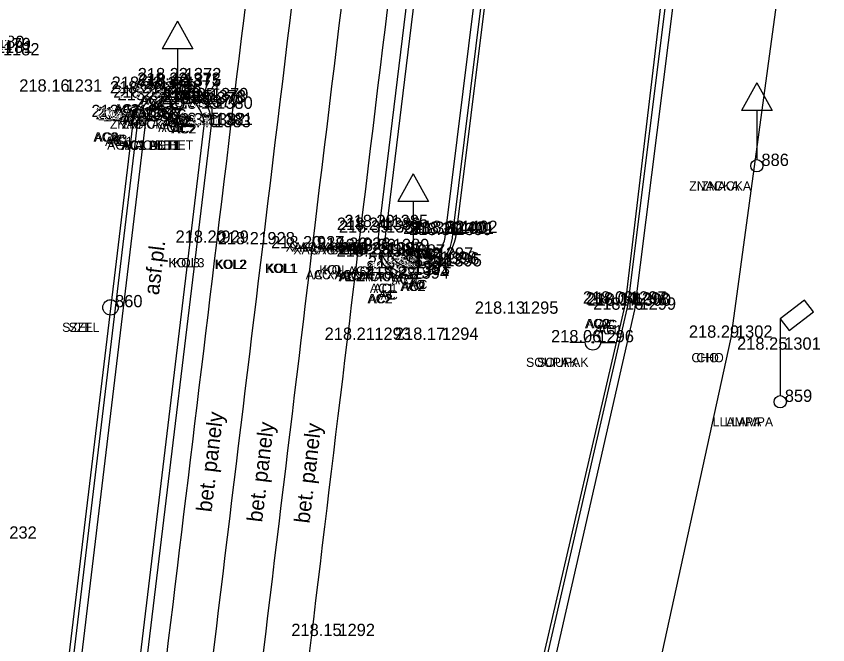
# Model space of a CAD drawing. Extents: x -471047 to -470889, y -1102859 to -1102000.
# Drawn here: x -470973.87 to -470947.45, y -1102478.75 to -1102458.3 of the extents above; entities that cross this region are included whole.
import ezdxf

# ---------------------------------------------------------------- set-up
doc = ezdxf.new("R2010")
doc.units = 0
for name, color, linetype in [('Vrstva 1', 7, 'Continuous'), ('Vrstva 11', 7, 'Continuous'), ('Vrstva 19', 7, 'Continuous'), ('Vrstva 22', 7, 'Continuous'), ('Vrstva 23', 7, 'Continuous'), ('Vrstva 34', 7, 'Continuous'), ('Vrstva 35', 7, 'Continuous'), ('Vrstva 36', 7, 'Continuous'), ('Vrstva 38', 7, 'Continuous'), ('Vrstva 5', 7, 'Continuous'), ('Vrstva 7', 7, 'Continuous'), ('Vrstva 8', 7, 'Continuous')]:
    doc.layers.add(name, color=color, linetype=linetype)

msp = doc.modelspace()

# ---------------------------------------------------------------- linework, layer by layer
at = {"layer": 'Vrstva 1'}
for points in [[(-471040.344, -1102858.385), (-471031.676, -1102846.187), (-471026.357, -1102838.629), (-471023.212, -1102833.975), (-471019.21, -1102827.465), (-471016.861, -1102823.272), (-471013.099, -1102815.912), (-471010.824, -1102810.955), (-471007.329, -1102802.292), (-471005.34, -1102796.515), (-471002.842, -1102787.838), (-471001.3, -1102780.997), (-471000.19, -1102774.713), (-470999.247, -1102768.204), (-470998.794, -1102764.784), (-470997.199, -1102751.812), (-470994.899, -1102732.807), (-470992.551, -1102713.262), (-470990.326, -1102694.887), (-470988.122, -1102676.57), (-470985.812, -1102657.305), (-470983.537, -1102638.407), (-470981.386, -1102620.622), (-470979.843, -1102608.014), (-470976.377, -1102579.253), (-470972.945, -1102550.69), (-470970.475, -1102530.206), (-470967.905, -1102508.801), (-470965.053, -1102485.131), (-470962.734, -1102465.9), (-470960.173, -1102444.812), (-470957.795, -1102425.103), (-470954.965, -1102401.839), (-470953.834, -1102392.574), (-470952.33, -1102379.985), (-470950.744, -1102366.853), (-470948.978, -1102352.106), (-470947.037, -1102335.844), (-470944.949, -1102318.462), (-470944.013, -1102310.745), (-470942.39, -1102297.267), (-470939.519, -1102273.45), (-470937.593, -1102257.43), (-470936.064, -1102244.81), (-470934.114, -1102228.634), (-470931.621, -1102207.856), (-470929.536, -1102190.857), (-470926.572, -1102166.31), (-470924.91, -1102152.663), (-470923.413, -1102140.333), (-470921.923, -1102127.669), (-470921.155, -1102120.084), (-470920.446, -1102109.574), (-470919.912, -1102099.137), (-470919.63, -1102088.981), (-470919.523, -1102081.193), (-470919.563, -1102070.395), (-470919.714, -1102064.236), (-470920.134, -1102054.704), (-470920.462, -1102047.615), (-470920.599, -1102044.52), (-470920.743, -1102041.873), (-470921.125, -1102034.455), (-470921.774, -1102030.337), (-470922.418, -1102027.787), (-470923.734, -1102023.93), (-470924.872, -1102021.434), (-470926.752, -1102018.182), (-470927.953, -1102016.45), (-470929.616, -1102014.424), (-470932.252, -1102011.756), (-470935.111, -1102009.425), (-470938.391, -1102007.371), (-470942.651, -1102005.401)], [(-471041.328, -1102857.18), (-471032.144, -1102844.242), (-471027.583, -1102837.763), (-471024.388, -1102833.028), (-471020.451, -1102826.6), (-471018.089, -1102822.378), (-471014.542, -1102815.445), (-471012.233, -1102810.418), (-471009.247, -1102803.108), (-471006.795, -1102796.098), (-471004.315, -1102787.532), (-471002.782, -1102780.723), (-471001.674, -1102774.458), (-471000.75, -1102768.095), (-471000.28, -1102764.601), (-470998.692, -1102751.741), (-470996.378, -1102732.635), (-470994.028, -1102713.058), (-470991.808, -1102694.749), (-470989.616, -1102676.447), (-470987.284, -1102657.013), (-470985.031, -1102638.272), (-470982.87, -1102620.431), (-470981.334, -1102607.933), (-470977.881, -1102579.263), (-470974.429, -1102550.492), (-470971.964, -1102530.054), (-470969.391, -1102508.607), (-470966.54, -1102484.984), (-470964.231, -1102465.853), (-470961.679, -1102444.752), (-470959.304, -1102425.078), (-470956.455, -1102401.634), (-470955.339, -1102392.489), (-470953.812, -1102379.71), (-470952.249, -1102366.808), (-470950.479, -1102352.023), (-470948.536, -1102335.868), (-470946.426, -1102318.233), (-470945.493, -1102310.531), (-470943.864, -1102297.013), (-470940.984, -1102273.071), (-470939.078, -1102257.195), (-470937.559, -1102244.684), (-470935.592, -1102228.353), (-470933.101, -1102207.653), (-470931.011, -1102190.57), (-470928.046, -1102166.021), (-470926.409, -1102152.578), (-470924.898, -1102140.121), (-470923.427, -1102127.544), (-470922.647, -1102119.826), (-470921.919, -1102109.229), (-470921.42, -1102099.134), (-470921.127, -1102089.016), (-470921.023, -1102081.453), (-470921.061, -1102070.468), (-470921.209, -1102064.314), (-470921.666, -1102053.966), (-470922.156, -1102043.345), (-470922.299, -1102039.934), (-470922.637, -1102034.36), (-470923.091, -1102031.241), (-470923.847, -1102028.247), (-470925.083, -1102024.594), (-470926.222, -1102022.086), (-470928.04, -1102018.943), (-470929.138, -1102017.357), (-470930.929, -1102015.175), (-470933.062, -1102013.049), (-470936.379, -1102010.368), (-470939.169, -1102008.662), (-470942.899, -1102006.906), (-470945.661, -1102005.908)], [(-471043.557, -1102855.955), (-471035.129, -1102844.026), (-471029.872, -1102836.499), (-471026.577, -1102831.578), (-471022.675, -1102825.415), (-471020.123, -1102821.053), (-471016.667, -1102814.59), (-471014.208, -1102809.45), (-471011.177, -1102802.451), (-471008.55, -1102795.333), (-471006.082, -1102787.209), (-471004.464, -1102780.376), (-471003.265, -1102774.167), (-471002.327, -1102767.948), (-471001.636, -1102762.527), (-471000.297, -1102751.605), (-470997.959, -1102732.524), (-470995.602, -1102712.802), (-470993.412, -1102694.623), (-470991.21, -1102676.17), (-470988.891, -1102656.857), (-470986.625, -1102638.083), (-470984.455, -1102620.195), (-470982.936, -1102607.733), (-470979.497, -1102579.223), (-470976.023, -1102550.279), (-470973.554, -1102529.822), (-470970.991, -1102508.497), (-470968.146, -1102484.787), (-470965.835, -1102465.72), (-470963.284, -1102444.529), (-470960.91, -1102424.942), (-470958.043, -1102401.343), (-470956.946, -1102392.356), (-470955.396, -1102379.408), (-470953.851, -1102366.636), (-470952.049, -1102351.733), (-470950.124, -1102335.611), (-470948.034, -1102318.083), (-470947.094, -1102310.328), (-470945.421, -1102296.51), (-470942.58, -1102272.848), (-470940.675, -1102256.948), (-470939.176, -1102244.526), (-470937.187, -1102228.174), (-470934.708, -1102207.467), (-470932.621, -1102190.433), (-470929.634, -1102165.778), (-470928.004, -1102152.415), (-470926.45, -1102139.595), (-470925.003, -1102127.418), (-470924.249, -1102119.695), (-470923.515, -1102109.093), (-470923.018, -1102099.069), (-470922.711, -1102088.911), (-470922.643, -1102081.356), (-470922.797, -1102070.414), (-470923.018, -1102064.454), (-470923.52, -1102053.203), (-470923.823, -1102047.529), (-470924.123, -1102041.506), (-470924.462, -1102037.486), (-470924.934, -1102031.904), (-470925.664, -1102028.672), (-470926.771, -1102025.506), (-470927.959, -1102022.914), (-470929.674, -1102020.028), (-470930.76, -1102018.498), (-470932.447, -1102016.478), (-470935.215, -1102013.816), (-470937.644, -1102011.98), (-470940.381, -1102010.371), (-470943.968, -1102008.669), (-470947.145, -1102007.524), (-470950.874, -1102006.74)], [(-471044.756, -1102855.056), (-471036.376, -1102843.177), (-471031.167, -1102835.741), (-471027.859, -1102830.8), (-471023.934, -1102824.593), (-471021.43, -1102820.312), (-471018.011, -1102813.91), (-471015.536, -1102808.75), (-471012.578, -1102801.897), (-471009.95, -1102794.77), (-471007.561, -1102786.914), (-471005.936, -1102780.074), (-471004.727, -1102773.818), (-471003.828, -1102767.827), (-471003.121, -1102762.345), (-471001.787, -1102751.467), (-470999.446, -1102732.348), (-470997.073, -1102712.539), (-470994.902, -1102694.521), (-470992.696, -1102676.023), (-470990.376, -1102656.68), (-470988.131, -1102638.071), (-470985.947, -1102620.018), (-470984.417, -1102607.512), (-470980.993, -1102579.08), (-470977.514, -1102550.137), (-470975.048, -1102529.649), (-470972.488, -1102508.37), (-470969.618, -1102484.508), (-470967.34, -1102465.669), (-470964.767, -1102444.39), (-470962.402, -1102424.781), (-470959.534, -1102401.193), (-470958.432, -1102392.151), (-470956.883, -1102379.208), (-470955.335, -1102366.424), (-470953.535, -1102351.506), (-470951.606, -1102335.399), (-470949.519, -1102317.94), (-470948.575, -1102310.159), (-470946.889, -1102296.144), (-470944.056, -1102272.618), (-470942.139, -1102256.659), (-470940.657, -1102244.341), (-470938.638, -1102227.749), (-470936.19, -1102207.298), (-470934.102, -1102190.255), (-470931.124, -1102165.639), (-470929.492, -1102152.254), (-470927.915, -1102139.252), (-470926.46, -1102127.103), (-470925.74, -1102119.604), (-470925.012, -1102108.913), (-470924.523, -1102099.054), (-470924.217, -1102088.866), (-470924.148, -1102081.334), (-470924.301, -1102070.391), (-470924.518, -1102064.43), (-470924.97, -1102054.435), (-470925.588, -1102041.569), (-470925.963, -1102035.313), (-470926.405, -1102032.225), (-470927.078, -1102029.198), (-470928.123, -1102026.148), (-470929.318, -1102023.558), (-470930.84, -1102020.97), (-470931.868, -1102019.515), (-470933.443, -1102017.605), (-470936.26, -1102014.885), (-470938.429, -1102013.255), (-470941.213, -1102011.639), (-470944.847, -1102009.927), (-470947.723, -1102008.912), (-470951.444, -1102008.161), (-470954.511, -1102007.931), (-470957.895, -1102008.041)]]:
    msp.add_spline(points, degree=3, dxfattribs=at)
at = {"layer": 'Vrstva 11'}
for p, q in [((-470955.349, -1102468.912), (-470955.849, -1102468.912)), ((-470954.849, -1102468.912), (-470954.349, -1102468.912))]:
    msp.add_line(p, q, dxfattribs=at)
for radius in [0.25, 0.025]:
    msp.add_circle((-470955.099, -1102468.912), radius, dxfattribs=at)
at = {"layer": 'Vrstva 19'}
for p, q in [((-470968.617, -1102458.459), (-470969.117, -1102459.359)), ((-470968.617, -1102458.459), (-470968.117, -1102459.359)), ((-470968.117, -1102459.359), (-470969.117, -1102459.359)), ((-470968.617, -1102459.359), (-470968.617, -1102460.959)), ((-470949.762, -1102460.465), (-470950.262, -1102461.365)), ((-470949.762, -1102460.465), (-470949.262, -1102461.365)), ((-470949.262, -1102461.365), (-470950.262, -1102461.365)), ((-470949.762, -1102461.365), (-470949.762, -1102462.965)), ((-470960.945, -1102463.422), (-470961.445, -1102464.322)), ((-470960.945, -1102463.422), (-470960.445, -1102464.322)), ((-470960.445, -1102464.322), (-470961.445, -1102464.322)), ((-470960.945, -1102464.322), (-470960.945, -1102465.922))]:
    msp.add_line(p, q, dxfattribs=at)
for centre in [(-470968.617, -1102461.159), (-470949.762, -1102463.165), (-470960.945, -1102466.122)]:
    msp.add_circle(centre, 0.2, dxfattribs=at)
at = {"layer": 'Vrstva 23'}
for p, q in [((-470948.206, -1102467.541), (-470949.001, -1102468.146)), ((-470947.916, -1102467.918), (-470948.206, -1102467.541)), ((-470948.714, -1102468.524), (-470947.916, -1102467.918)), ((-470949.001, -1102468.146), (-470949.001, -1102470.646)), ((-470949.001, -1102468.146), (-470948.714, -1102468.524))]:
    msp.add_line(p, q, dxfattribs=at)
for centre, radius in [((-470970.801, -1102467.773), 0.25), ((-470949.001, -1102470.846), 0.2)]:
    msp.add_circle(centre, radius, dxfattribs=at)
at = {"layer": 'Vrstva 34'}
for p, q in [((-470968.53, -1102460.38), (-470968.53, -1102460.38)), ((-470969.38, -1102460.66), (-470969.38, -1102460.66)), ((-470968.55, -1102460.53), (-470968.55, -1102460.53)), ((-470968.54, -1102460.58), (-470968.54, -1102460.58)), ((-470972.41, -1102460.75), (-470972.41, -1102460.75)), ((-470969.35, -1102460.81), (-470969.35, -1102460.81)), ((-470969.35, -1102460.95), (-470969.35, -1102460.95)), ((-470968.58, -1102460.78), (-470968.58, -1102460.78)), ((-470969.21, -1102461.03), (-470969.21, -1102461.03)), ((-470968.62, -1102461.16), (-470968.62, -1102461.16)), ((-470967.93, -1102461.26), (-470967.93, -1102461.26)), ((-470967.8, -1102461.16), (-470967.8, -1102461.16)), ((-470967.73, -1102461.1), (-470967.73, -1102461.1)), ((-470967.65, -1102461.03), (-470967.65, -1102461.03)), ((-470967.51, -1102461.31), (-470967.51, -1102461.31)), ((-470970.04, -1102461.58), (-470970.04, -1102461.58)), ((-470969.9, -1102461.65), (-470969.9, -1102461.65)), ((-470969.83, -1102461.68), (-470969.83, -1102461.68)), ((-470969.66, -1102461.72), (-470969.66, -1102461.72)), ((-470967.75, -1102461.85), (-470967.75, -1102461.85)), ((-470967.57, -1102461.91), (-470967.57, -1102461.91)), ((-470967.51, -1102461.84), (-470967.51, -1102461.84)), ((-470949.76, -1102463.17), (-470949.76, -1102463.17)), ((-470961.8, -1102465.16), (-470961.8, -1102465.16)), ((-470962.05, -1102465.25), (-470962.05, -1102465.25)), ((-470961.98, -1102465.34), (-470961.98, -1102465.34)), ((-470959.89, -1102465.38), (-470959.89, -1102465.38)), ((-470959.72, -1102465.42), (-470959.72, -1102465.42)), ((-470959.66, -1102465.38), (-470959.66, -1102465.38)), ((-470959.54, -1102465.35), (-470959.54, -1102465.35)), ((-470967.34, -1102465.67), (-470967.34, -1102465.67)), ((-470965.84, -1102465.72), (-470965.84, -1102465.72)), ((-470964.23, -1102465.85), (-470964.23, -1102465.85)), ((-470962.73, -1102465.9), (-470962.73, -1102465.9)), ((-470961.76, -1102465.94), (-470961.76, -1102465.94)), ((-470962.06, -1102466.12), (-470962.06, -1102466.12)), ((-470961.97, -1102466.06), (-470961.97, -1102466.06)), ((-470961.92, -1102466.05), (-470961.92, -1102466.05)), ((-470960.95, -1102466.12), (-470960.95, -1102466.12)), ((-470960.33, -1102466.22), (-470960.33, -1102466.22)), ((-470961.04, -1102466.5), (-470961.04, -1102466.5)), ((-470960.22, -1102466.35), (-470960.22, -1102466.35)), ((-470960.13, -1102466.38), (-470960.13, -1102466.38)), ((-470960.05, -1102466.44), (-470960.05, -1102466.44)), ((-470961.09, -1102466.66), (-470961.09, -1102466.66)), ((-470961.09, -1102466.72), (-470961.09, -1102466.72)), ((-470961.12, -1102466.84), (-470961.12, -1102466.84)), ((-470970.8, -1102467.77), (-470970.8, -1102467.77)), ((-470954.04, -1102467.65), (-470954.04, -1102467.65)), ((-470953.95, -1102467.68), (-470953.95, -1102467.68)), ((-470953.89, -1102467.72), (-470953.89, -1102467.72)), ((-470953.73, -1102467.85), (-470953.73, -1102467.85)), ((-470957.56, -1102467.98), (-470957.56, -1102467.98)), ((-470962.36, -1102468.83), (-470962.36, -1102468.83)), ((-470960.16, -1102468.83), (-470960.16, -1102468.83)), ((-470955.1, -1102468.91), (-470955.1, -1102468.91)), ((-470950.59, -1102468.76), (-470950.59, -1102468.76)), ((-470949.02, -1102469.15), (-470949.02, -1102469.15)), ((-470949, -1102470.85), (-470949, -1102470.85)), ((-470963.53, -1102478.47), (-470963.53, -1102478.47))]:
    msp.add_line(p, q, dxfattribs=at)
at = {"layer": 'Vrstva 5'}
for p, q in [((-470959.536, -1102465.35), (-470957.491, -1102448.938)), ((-470954.037, -1102467.653), (-470951.83, -1102449.069)), ((-470967.507, -1102461.31), (-470967.509, -1102461.842)), ((-470972.503, -1102482.091), (-470970.044, -1102461.58)), ((-470961.965, -1102466.061), (-470962.062, -1102466.116)), ((-470956.777, -1102479.435), (-470954.037, -1102467.653))]:
    msp.add_line(p, q, dxfattribs=at)
for centre, radius, start, end in [((-470968.456, -1102462.026), 1.649, 92.6792, 164.3252), ((-470968.922, -1102461.837), 1.509, 20.4159, 75.0812)]:
    msp.add_arc(centre, radius, start, end, dxfattribs=at)
at = {"layer": 'Vrstva 7'}
for p, q in [((-470961.805, -1102465.162), (-470959.783, -1102448.626)), ((-470959.894, -1102465.384), (-470957.865, -1102448.933)), ((-470953.729, -1102467.848), (-470951.395, -1102449.228)), ((-470972.098, -1102482.131), (-470969.655, -1102461.72)), ((-470970.234, -1102482.541), (-470967.747, -1102461.853)), ((-470956.386, -1102479.473), (-470953.729, -1102467.848))]:
    msp.add_line(p, q, dxfattribs=at)
for centre, radius, start, end in [((-470968.456, -1102462.006), 1.232, 95.668, 166.5606), ((-470968.897, -1102461.885), 1.15, 1.5947, 73.9183), ((-470960.828, -1102465.491), 1.031, 161.3791, 257.9166), ((-470961.109, -1102465.282), 1.219, 273.0505, 355.179)]:
    msp.add_arc(centre, radius, start, end, dxfattribs=at)
at = {"layer": 'Vrstva 8'}
for p, q in [((-470962.05, -1102465.251), (-470960.033, -1102448.587)), ((-470959.656, -1102465.384), (-470957.621, -1102448.918)), ((-470953.953, -1102467.677), (-470951.633, -1102449.156)), ((-470950.592, -1102468.764), (-470948.019, -1102449.764)), ((-470972.348, -1102482.071), (-470969.899, -1102461.647)), ((-470970.009, -1102482.55), (-470967.509, -1102461.842)), ((-470956.653, -1102479.445), (-470953.953, -1102467.677)), ((-470953.088, -1102480.135), (-470950.592, -1102468.764))]:
    msp.add_line(p, q, dxfattribs=at)
for centre, radius, start, end in [((-470968.507, -1102461.955), 1.425, 91.9216, 167.5384), ((-470968.831, -1102461.823), 1.322, 359.1738, 77.9539), ((-470960.884, -1102465.538), 1.201, 166.1717, 260.3049), ((-470961.05, -1102465.328), 1.395, 268.5039, 357.6888), ((-470961.545, -1102465.061), 2.029, 317.2268, 351.8097), ((-470960.958, -1102465.652), 1.197, 202.7767, 318.9381)]:
    msp.add_arc(centre, radius, start, end, dxfattribs=at)

# ---------------------------------------------------------------- texts
at = {"layer": 'Vrstva 22'}
for s, rotation, p in [('asf.pl.', 83.0293, (-470969.229, -1102467.39)), ('bet. panely', 83.1381, (-470967.513, -1102474.453)), ('bet. panely', 83.1381, (-470965.864, -1102474.782)), ('bet. panely', 83.1381, (-470964.325, -1102474.819))]:
    msp.add_text(s, height=0.5, rotation=rotation, dxfattribs=at).set_placement(p)
at = {"layer": 'Vrstva 35'}
for s, p in [('AC2', (-470969.846, -1102461.18)), ('AC2', (-470969.805, -1102461.18)), ('AC2', (-470970.696, -1102461.46)), ('AC2', (-470970.655, -1102461.46)), ('AC1', (-470969.897, -1102461.58)), ('AC1', (-470969.78, -1102461.58)), ('AC', (-470969.539, -1102461.33)), ('AC', (-470969.464, -1102461.33)), ('AC1', (-470970.527, -1102461.83)), ('AC1', (-470970.41, -1102461.83)), ('AC', (-470970.339, -1102461.61)), ('AC', (-470970.264, -1102461.61)), ('AC2', (-470968.966, -1102461.83)), ('AC2', (-470968.925, -1102461.83)), ('ZNACKA', (-470970.82, -1102461.96)), ('ZNACKA', (-470970.434, -1102461.96)), ('AC1', (-470969.247, -1102462.06)), ('AC1', (-470969.13, -1102462.06)), ('AC2', (-470968.826, -1102462.11)), ('AC2', (-470968.785, -1102462.11)), ('AC', (-470968.719, -1102461.9)), ('AC', (-470968.644, -1102461.9)), ('AC2', (-470971.356, -1102462.38)), ('AC2', (-470971.315, -1102462.38)), ('AC1', (-470970.977, -1102462.52)), ('AC', (-470970.889, -1102462.45)), ('AC1', (-470970.86, -1102462.52)), ('AC', (-470970.814, -1102462.45)), ('AC2 AC BET', (-470970.91, -1102462.64)), ('AC2 AC BET', (-470970.45, -1102462.64)), ('AC1 BET1', (-470970.45, -1102462.65)), ('AC1 BET1', (-470970.417, -1102462.65)), ('ZNACKA', (-470951.96, -1102463.97)), ('ZNACKA', (-470951.574, -1102463.97)), ('XAC1 XBET1', (-470965.1, -1102465.96)), ('XAC1 XBET1', (-470964.917, -1102465.96)), ('XAC XBET', (-470964.85, -1102466.05)), ('XAC XBET', (-470964.314, -1102466.05)), ('AC1', (-470961.207, -1102466.18)), ('AC1', (-470961.09, -1102466.18)), ('AC2', (-470960.856, -1102466.15)), ('AC2', (-470960.815, -1102466.15)), ('AC', (-470960.649, -1102466.18)), ('AC', (-470960.574, -1102466.18)), ('KOL3', (-470968.915, -1102466.47)), ('KOL3', (-470968.768, -1102466.47)), ('KOL2', (-470967.415, -1102466.52)), ('KOL2', (-470967.381, -1102466.52)), ('KOL1', (-470965.772, -1102466.65)), ('KOL1', (-470965.73, -1102466.65)), ('AC XAC2', (-470964.445, -1102466.86)), ('AC XAC2', (-470964.186, -1102466.86)), ('KOL', (-470964.005, -1102466.7)), ('KOL', (-470963.869, -1102466.7)), ('AC1', (-470963.077, -1102466.74)), ('AC1', (-470962.96, -1102466.74)), ('AC2', (-470963.376, -1102466.92)), ('AC2', (-470963.335, -1102466.92)), ('ZNACKA', (-470963.15, -1102466.92)), ('ZNACKA', (-470962.764, -1102466.92)), ('AC1', (-470961.647, -1102467.02)), ('AC1', (-470961.53, -1102467.02)), ('AC1', (-470962.357, -1102467.3)), ('AC1', (-470962.24, -1102467.3)), ('AC2', (-470961.366, -1102467.24)), ('AC2', (-470961.325, -1102467.24)), ('AC', (-470961.119, -1102467.18)), ('AC', (-470961.044, -1102467.18)), ('AC2', (-470962.436, -1102467.64)), ('AC2', (-470962.395, -1102467.64)), ('AC', (-470962.079, -1102467.52)), ('AC', (-470962.004, -1102467.52)), ('AC2', (-470955.356, -1102468.45)), ('AC2', (-470955.315, -1102468.45)), ('SZEL', (-470972.375, -1102468.57)), ('SZEL', (-470972.164, -1102468.57)), ('AC1', (-470955.047, -1102468.65)), ('AC', (-470954.939, -1102468.48)), ('AC1', (-470954.93, -1102468.65)), ('AC', (-470954.864, -1102468.48)), ('SOUPAK', (-470957.275, -1102469.71)), ('SOUPAK', (-470956.914, -1102469.71)), ('CHO', (-470951.891, -1102469.56)), ('CHO', (-470951.729, -1102469.56)), ('LLAMPA', (-470951.2, -1102471.65)), ('LLAMPA', (-470950.814, -1102471.65))]:
    msp.add_text(s, height=0.3, dxfattribs=at).set_placement(p)
at = {"layer": 'Vrstva 36'}
for s, p in [(' 1180', (-470974.94, -1102459.33)), (' 1179', (-470974.73, -1102459.4)), (' 1181', (-470974.68, -1102459.49)), (' 1182', (-470974.45, -1102459.57)), (' 1373', (-470968.55, -1102460.53)), (' 1375', (-470968.54, -1102460.58)), (' 1372', (-470968.53, -1102460.38)), (' 1231', (-470972.41, -1102460.75)), (' 1371', (-470969.38, -1102460.66)), (' 1370', (-470969.35, -1102460.81)), (' 1374', (-470968.58, -1102460.78)), (' 1368', (-470969.35, -1102460.95)), (' 1369', (-470969.21, -1102461.03)), (' 1378', (-470967.73, -1102461.1)), (' 1379', (-470967.65, -1102461.03)), (' 888', (-470968.62, -1102461.16)), (' 1377', (-470967.93, -1102461.26)), (' 1376', (-470967.8, -1102461.16)), (' 1380', (-470967.51, -1102461.31)), (' 1364', (-470970.04, -1102461.58)), (' 1365', (-470969.9, -1102461.65)), (' 1367', (-470969.83, -1102461.68)), (' 1366', (-470969.66, -1102461.72)), (' 1382', (-470967.75, -1102461.85)), (' 1383', (-470967.57, -1102461.91)), (' 1381', (-470967.51, -1102461.84)), (' 886', (-470949.76, -1102463.17)), (' 1386', (-470962.05, -1102465.25)), (' 1384', (-470961.98, -1102465.34)), (' 1385', (-470961.8, -1102465.16)), (' 1400', (-470959.89, -1102465.38)), (' 1401', (-470959.66, -1102465.38)), (' 1402', (-470959.54, -1102465.35)), (' 1399', (-470959.72, -1102465.42)), (' 929', (-470967.34, -1102465.67)), (' 928', (-470965.84, -1102465.72)), (' 927', (-470964.23, -1102465.85)), (' 926', (-470962.73, -1102465.9)), (' 1388', (-470962.06, -1102466.12)), (' 1387', (-470961.97, -1102466.06)), (' 1390', (-470961.92, -1102466.05)), (' 1389', (-470961.76, -1102465.94)), (' 887', (-470960.95, -1102466.12)), (' 1397', (-470960.33, -1102466.22)), (' 1398', (-470960.22, -1102466.35)), (' 1396', (-470960.13, -1102466.38)), (' 1391', (-470961.09, -1102466.66)), (' 1392', (-470961.04, -1102466.5)), (' 1395', (-470960.05, -1102466.44)), (' 1394', (-470961.12, -1102466.84)), (' 1393', (-470961.09, -1102466.72)), (' 1297', (-470954.04, -1102467.65)), (' 1298', (-470953.95, -1102467.68)), (' 1300', (-470953.89, -1102467.72)), (' 860', (-470970.8, -1102467.77)), (' 1295', (-470957.56, -1102467.98)), (' 1299', (-470953.73, -1102467.85)), (' 1302', (-470950.59, -1102468.76)), (' 1293', (-470962.36, -1102468.83)), (' 1294', (-470960.16, -1102468.83)), (' 1296', (-470955.1, -1102468.91)), (' 1301', (-470949.02, -1102469.15)), (' 859', (-470949, -1102470.85)), (' 1232', (-470974.54, -1102475.3)), (' 1292', (-470963.53, -1102478.47))]:
    msp.add_text(s, height=0.4, dxfattribs=at).set_placement(p)
at = {"layer": 'Vrstva 38'}
for s, p in [('218.22 ', (-470969.931, -1102460.53)), ('218.23 ', (-470969.913, -1102460.38)), ('218.40 ', (-470969.883, -1102460.58)), ('218.16 ', (-470973.77, -1102460.75)), ('218.21 ', (-470970.82, -1102460.81)), ('218.23 ', (-470970.763, -1102460.66)), ('218.38 ', (-470969.964, -1102460.78)), ('218.36 ', (-470970.71, -1102460.95)), ('218.36 ', (-470970.57, -1102461.03)), ('218.25 ', (-470969.114, -1102461.1)), ('218.25 ', (-470969.034, -1102461.03)), ('218.39 ', (-470969.314, -1102461.26)), ('218.40 ', (-470969.143, -1102461.16)), ('218.25 ', (-470968.894, -1102461.31)), ('218.19 ', (-470971.424, -1102461.58)), ('218.18 ', (-470971.284, -1102461.65)), ('218.34 ', (-470971.212, -1102461.68)), ('218.33 ', (-470971.043, -1102461.72)), ('218.39 ', (-470969.134, -1102461.85)), ('218.40 ', (-470968.913, -1102461.91)), ('218.25 ', (-470968.894, -1102461.84)), ('218.24 ', (-470963.432, -1102465.25)), ('218.39 ', (-470963.364, -1102465.34)), ('218.39 ', (-470963.184, -1102465.16)), ('218.35 ', (-470961.274, -1102465.38)), ('218.20 ', (-470961.003, -1102465.38)), ('218.22 ', (-470960.921, -1102465.35)), ('218.36 ', (-470961.08, -1102465.42)), ('218.20 ', (-470968.683, -1102465.67)), ('218.21 ', (-470967.31, -1102465.72)), ('218.20 ', (-470965.573, -1102465.85)), ('218.20 ', (-470964.073, -1102465.9)), ('218.22 ', (-470963.441, -1102466.12)), ('218.25 ', (-470963.354, -1102466.06)), ('218.38 ', (-470963.304, -1102466.05)), ('218.39 ', (-470963.144, -1102465.94)), ('218.36 ', (-470961.69, -1102466.22)), ('218.21 ', (-470961.6, -1102466.38)), ('218.36 ', (-470961.58, -1102466.35)), ('218.38 ', (-470962.474, -1102466.66)), ('218.37 ', (-470962.423, -1102466.5)), ('218.21 ', (-470961.52, -1102466.44)), ('218.22 ', (-470962.501, -1102466.84)), ('218.23 ', (-470962.473, -1102466.72)), ('218.08 ', (-470955.424, -1102467.65)), ('218.04 ', (-470955.332, -1102467.68)), ('218.17 ', (-470955.273, -1102467.72)), ('218.13 ', (-470958.943, -1102467.98)), ('218.16 ', (-470955.09, -1102467.85)), ('218.29 ', (-470951.974, -1102468.76)), ('218.21 ', (-470963.83, -1102468.83)), ('218.17 ', (-470961.543, -1102468.83)), ('218.06 ', (-470956.46, -1102468.91)), ('218.25 ', (-470950.404, -1102469.15)), ('218.15 ', (-470964.914, -1102478.47))]:
    msp.add_text(s, height=0.4, dxfattribs=at).set_placement(p)

doc.saveas('drawing.dxf')
